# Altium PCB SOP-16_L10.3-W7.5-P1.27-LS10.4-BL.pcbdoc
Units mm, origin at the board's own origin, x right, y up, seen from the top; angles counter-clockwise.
Board outline 23.35 x 25 mm, 2 copper layers (Top Layer, Bottom Layer), stack 0 mm thick; 1 components, 0 nets, 16 pads, 0 vias.
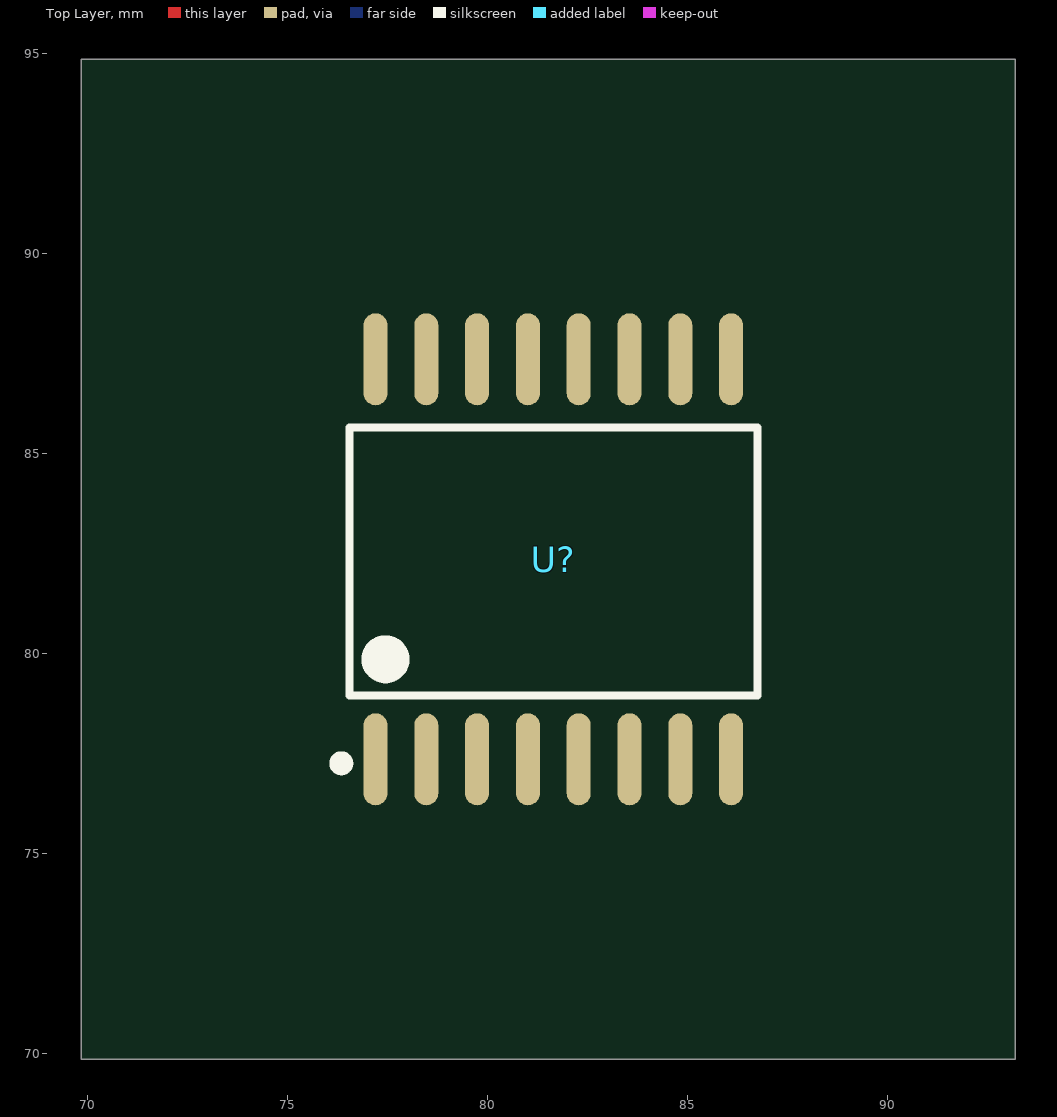
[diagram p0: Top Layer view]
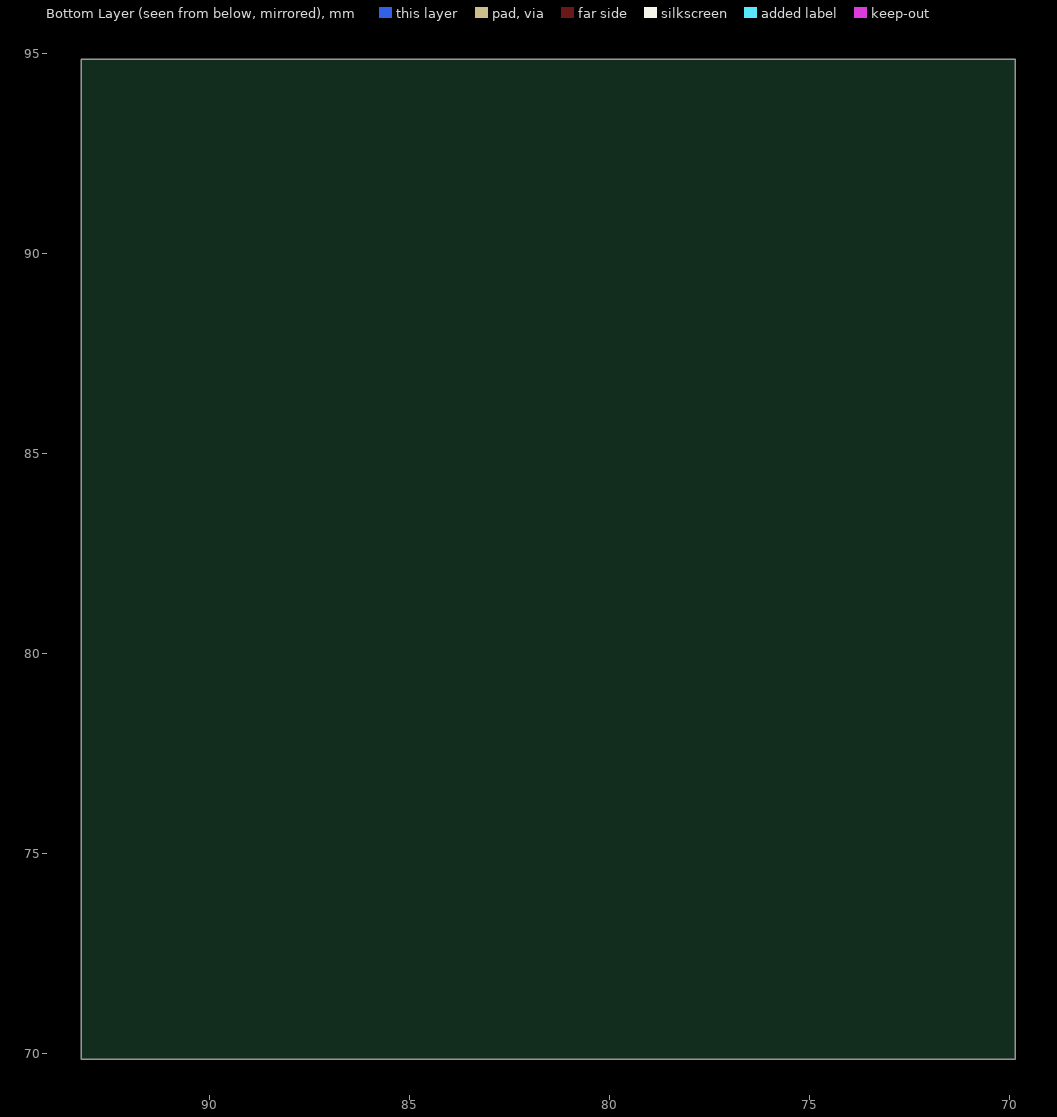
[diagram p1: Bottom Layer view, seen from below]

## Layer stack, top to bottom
Top Layer: signal copper (thickness not stored)
Bottom Layer: signal copper (thickness not stored)

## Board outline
93.2,69.85 69.85,69.85 69.85,94.85 93.2,94.85

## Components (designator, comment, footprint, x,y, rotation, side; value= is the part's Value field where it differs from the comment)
U? "" SOP-16_L10.3-W7.5-P1.27-LS10.4-BL 81.65,82.35 r0 top

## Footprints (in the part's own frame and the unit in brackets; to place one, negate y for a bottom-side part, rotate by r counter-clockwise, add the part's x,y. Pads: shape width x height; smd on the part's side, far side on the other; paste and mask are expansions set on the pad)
SOP-16_L10.3-W7.5-P1.27-LS10.4-BL [mm]
  oval 0.6x2.3 smd: 1(-4.445,-5) 2(-3.175,-5) 3(-1.905,-5) 4(-0.635,-5) 5(0.635,-5) 6(1.905,-5) 7(3.175,-5) 8(4.445,-5) 9(4.445,5) 10(3.175,5) 11(1.905,5) 12(0.635,5) 13(-0.635,5) 14(-1.905,5) 15(-3.175,5) 16(-4.445,5)
  silkscreen extent -5.45,-5.25 5.1,3.3

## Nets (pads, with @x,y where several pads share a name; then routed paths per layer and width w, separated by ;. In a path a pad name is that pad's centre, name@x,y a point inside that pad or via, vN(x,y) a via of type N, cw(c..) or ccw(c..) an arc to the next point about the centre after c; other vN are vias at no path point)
pads on no net: U?.1 U?.2 U?.3 U?.4 U?.5 U?.6 U?.7 U?.8 U?.9 U?.10 U?.11 U?.12 U?.13 U?.14 U?.15 U?.16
